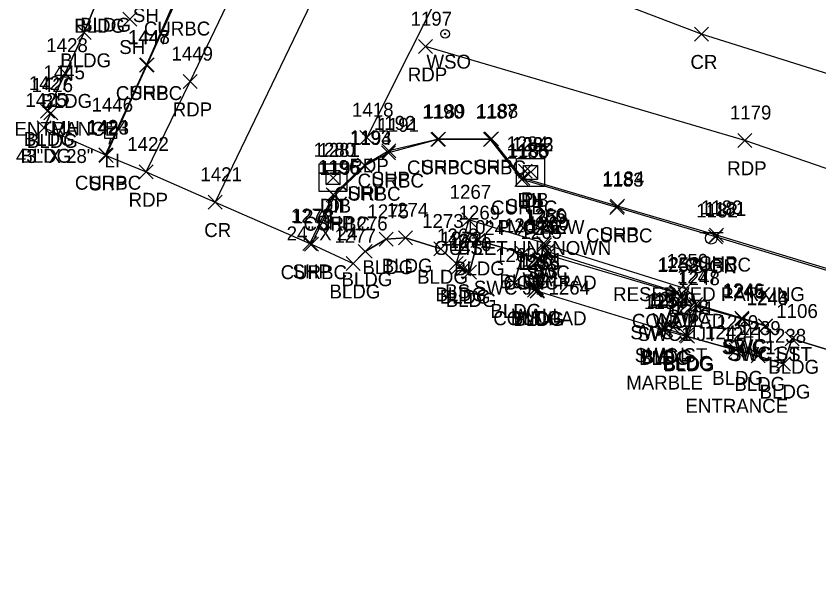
# Model space of a CAD drawing. Extents: x 1462668 to 1465147, y 550359 to 557351.
# Drawn here: x 1464553.4 to 1464668.5, y 552389.3 to 552470.8 of the extents above; entities that cross this region are included whole.
import ezdxf

# ---------------------------------------------------------------- set-up
doc = ezdxf.new("R2010")
doc.units = 0
for name, color, linetype in [('D_A', 7, 'Continuous'), ('D_C', 7, 'Continuous'), ('D_I', 7, 'Continuous'), ('D_TIC', 7, 'Continuous'), ('DS', 7, 'Continuous'), ('L_A', 7, 'Continuous'), ('L_C', 7, 'Continuous'), ('L_I', 7, 'Continuous'), ('L_TIC', 7, 'Continuous'), ('LBC', 7, 'Continuous'), ('LELB', 7, 'Continuous'), ('Level 6', 7, 'Continuous'), ('LS', 7, 'Continuous'), ('LW', 7, 'Continuous'), ('P_A', 7, 'Continuous'), ('P_I', 7, 'Continuous'), ('P_TIC', 7, 'Continuous'), ('PET', 7, 'Continuous'), ('PRC', 7, 'Continuous'), ('PSP', 7, 'Continuous'), ('R_A', 7, 'Continuous'), ('R_I', 7, 'Continuous'), ('R_TIC', 7, 'Continuous'), ('RC', 7, 'Continuous'), ('RSW', 7, 'Continuous'), ('S_A', 7, 'Continuous'), ('S_C', 7, 'Continuous'), ('S_I', 7, 'Continuous'), ('SSGN', 7, 'Continuous'), ('U_A', 7, 'Continuous'), ('U_C', 7, 'Continuous'), ('U_I', 7, 'Continuous'), ('ULP', 7, 'Continuous'), ('UUMH', 7, 'Continuous'), ('UWV', 7, 'Continuous')]:
    doc.layers.add(name, color=color, linetype=linetype)

msp = doc.modelspace()

# ---------------------------------------------------------------- linework, layer by layer
at = {"layer": 'D_TIC'}
for points in [[(1464597.88, 552446.64), (1464599.88, 552448.64)], [(1464599.88, 552446.64), (1464597.88, 552448.64)], [(1464625.43, 552447.58), (1464627.43, 552449.58)], [(1464627.43, 552447.58), (1464625.43, 552449.58)], [(1464626.22, 552447.48), (1464628.22, 552449.48)], [(1464628.22, 552447.48), (1464626.22, 552449.48)]]:
    msp.add_lwpolyline(points, dxfattribs=at)
at = {"layer": 'DS'}
for p, q in [((1464625.18, 552450.42), (1464629.18, 552450.42)), ((1464625.18, 552446.42), (1464625.18, 552450.42)), ((1464629.18, 552450.42), (1464629.18, 552446.42)), ((1464596.85, 552449.67), (1464600.85, 552449.67)), ((1464596.85, 552445.67), (1464596.85, 552449.67)), ((1464597.85, 552446.67), (1464597.85, 552448.67)), ((1464597.85, 552448.67), (1464599.85, 552448.67)), ((1464599.85, 552448.67), (1464599.85, 552446.67)), ((1464600.85, 552449.67), (1464600.85, 552445.67)), ((1464626.18, 552447.42), (1464626.18, 552449.42)), ((1464626.18, 552449.42), (1464628.18, 552449.42)), ((1464628.18, 552449.42), (1464628.18, 552447.42)), ((1464598.85, 552447.67), (1464598.85, 552447.67)), ((1464598.85, 552447.67), (1464598.85, 552447.67)), ((1464627.19, 552448.42), (1464627.19, 552448.42)), ((1464627.19, 552448.42), (1464627.19, 552448.42)), ((1464599.85, 552446.67), (1464597.85, 552446.67)), ((1464629.18, 552446.42), (1464625.18, 552446.42)), ((1464628.18, 552447.42), (1464626.18, 552447.42)), ((1464600.85, 552445.67), (1464596.85, 552445.67))]:
    msp.add_line(p, q, dxfattribs=at)
at = {"layer": 'L_TIC'}
for points in [[(1464568.73, 552469.4), (1464570.73, 552471.4)], [(1464570.73, 552469.4), (1464568.73, 552471.4)], [(1464562.16, 552467.49), (1464564.16, 552469.49)], [(1464564.16, 552467.49), (1464562.16, 552469.49)], [(1464559.44, 552461.67), (1464561.44, 552463.67)], [(1464561.44, 552461.67), (1464559.44, 552463.67)], [(1464556.94, 552456.22), (1464558.94, 552458.22)], [(1464558.94, 552456.22), (1464556.94, 552458.22)], [(1464557.38, 552455.94), (1464559.38, 552457.94)], [(1464559.38, 552455.94), (1464557.38, 552457.94)], [(1464556.45, 552453.8), (1464558.45, 552455.8)], [(1464558.45, 552453.8), (1464556.45, 552455.8)], [(1464617.32, 552440.63), (1464619.32, 552442.63)], [(1464619.32, 552440.63), (1464617.32, 552442.63)], [(1464605.48, 552437.83), (1464607.48, 552439.83)], [(1464607.48, 552437.83), (1464605.48, 552439.83)], [(1464608.25, 552438.05), (1464610.25, 552440.05)], [(1464610.25, 552438.05), (1464608.25, 552440.05)], [(1464618.61, 552437.65), (1464620.61, 552439.65)], [(1464620.61, 552437.65), (1464618.61, 552439.65)], [(1464613.32, 552436.45), (1464615.32, 552438.45)], [(1464615.32, 552436.45), (1464613.32, 552438.45)], [(1464628.07, 552437.27), (1464630.07, 552439.27)], [(1464630.07, 552437.27), (1464628.07, 552439.27)], [(1464602.48, 552436.1), (1464604.48, 552438.1)], [(1464604.48, 552436.1), (1464602.48, 552438.1)], [(1464625.11, 552435.81), (1464627.11, 552437.81)], [(1464627.11, 552435.81), (1464625.11, 552437.81)], [(1464628.53, 552436.1), (1464630.53, 552438.1)], [(1464630.53, 552436.1), (1464628.53, 552438.1)], [(1464628.64, 552435.62), (1464630.64, 552437.62)], [(1464630.64, 552435.62), (1464628.64, 552437.62)], [(1464600.76, 552434.34), (1464602.76, 552436.34)], [(1464602.76, 552434.34), (1464600.76, 552436.34)], [(1464615.5, 552434.37), (1464617.5, 552436.37)], [(1464617.5, 552434.37), (1464615.5, 552436.37)], [(1464615.95, 552433.93), (1464617.95, 552435.93)], [(1464617.95, 552433.93), (1464615.95, 552435.93)], [(1464616.56, 552433.6), (1464618.56, 552435.6)], [(1464618.56, 552433.6), (1464616.56, 552435.6)], [(1464617.42, 552433.13), (1464619.42, 552435.13)], [(1464619.42, 552433.13), (1464617.42, 552435.13)], [(1464623.84, 552431.56), (1464625.84, 552433.56)], [(1464625.84, 552431.56), (1464623.84, 552433.56)], [(1464626.73, 552430.54), (1464628.73, 552432.54)], [(1464628.73, 552430.54), (1464626.73, 552432.54)], [(1464627.01, 552430.88), (1464629.01, 552432.88)], [(1464629.01, 552430.88), (1464627.01, 552432.88)], [(1464627.19, 552430.5), (1464629.19, 552432.5)], [(1464629.19, 552430.5), (1464627.19, 552432.5)], [(1464627.12, 552430.4), (1464629.12, 552432.4)], [(1464629.12, 552430.4), (1464627.12, 552432.4)], [(1464647.05, 552430.14), (1464649.05, 552432.14)], [(1464649.05, 552430.14), (1464647.05, 552432.14)], [(1464647.17, 552430.26), (1464649.17, 552432.26)], [(1464649.17, 552430.26), (1464647.17, 552432.26)], [(1464645.15, 552424.82), (1464647.15, 552426.82)], [(1464647.15, 552424.82), (1464645.15, 552426.82)], [(1464645.33, 552425.28), (1464647.33, 552427.28)], [(1464647.33, 552425.28), (1464645.33, 552427.28)], [(1464645.51, 552424.99), (1464647.51, 552426.99)], [(1464647.51, 552424.99), (1464645.51, 552426.99)], [(1464648.5, 552424.09), (1464650.5, 552426.09)], [(1464650.5, 552424.09), (1464648.5, 552426.09)], [(1464648.66, 552423.91), (1464650.66, 552425.91)], [(1464650.66, 552423.91), (1464648.66, 552425.91)], [(1464663.67, 552423.54), (1464665.67, 552425.54)], [(1464665.67, 552423.54), (1464663.67, 552425.54)], [(1464655.63, 552421.95), (1464657.63, 552423.95)], [(1464657.63, 552421.95), (1464655.63, 552423.95)], [(1464658.8, 552421.09), (1464660.8, 552423.09)], [(1464660.8, 552421.09), (1464658.8, 552423.09)], [(1464662.42, 552419.98), (1464664.42, 552421.98)], [(1464664.42, 552419.98), (1464662.42, 552421.98)]]:
    msp.add_lwpolyline(points, dxfattribs=at)
at = {"layer": 'LBC'}
for points in [[(1464557.45, 552454.8), (1464558.38, 552456.94), (1464557.94, 552457.22), (1464560.44, 552462.67), (1464563.16, 552468.49), (1464565.17, 552473.45)], [(1464614.32, 552437.45), (1464609.25, 552439.05), (1464606.48, 552438.83), (1464603.48, 552437.1), (1464601.76, 552435.34)], [(1464675.46, 552421.24), (1464664.67, 552424.54), (1464663.42, 552420.98), (1464659.8, 552422.09), (1464656.63, 552422.95), (1464649.66, 552424.91), (1464649.5, 552425.09), (1464646.51, 552425.99), (1464646.15, 552425.82), (1464628.12, 552431.4), (1464627.73, 552431.54), (1464624.84, 552432.56), (1464626.11, 552436.81), (1464619.61, 552438.65), (1464618.42, 552434.13), (1464617.56, 552434.6), (1464616.95, 552434.93)], [(1464614.32, 552437.45), (1464616.5, 552435.37)], [(1464616.95, 552434.93), (1464616.5, 552435.37)]]:
    msp.add_lwpolyline(points, dxfattribs=at)
at = {"layer": 'LELB'}
msp.add_lwpolyline([(1464629.07, 552438.27), (1464618.32, 552441.63), (1464616.5, 552435.37)], dxfattribs=at)
at = {"layer": 'Level 6'}
msp.add_lwpolyline([(1464565.17, 552473.45), (1464563.16, 552468.49), (1464560.44, 552462.67), (1464557.94, 552457.22), (1464558.38, 552456.94), (1464557.45, 552454.8), (1464566.26, 552450.94), (1464566.35, 552450.84), (1464572.06, 552448.49), (1464581.96, 552444.15), (1464595.53, 552438.22), (1464595.76, 552438.11), (1464601.76, 552435.34), (1464603.48, 552437.1), (1464606.48, 552438.83), (1464609.25, 552439.05), (1464614.32, 552437.45), (1464616.5, 552435.37), (1464616.95, 552434.93), (1464617.56, 552434.6), (1464618.42, 552434.13), (1464619.61, 552438.65), (1464626.11, 552436.81), (1464624.84, 552432.56), (1464627.73, 552431.54), (1464628.12, 552431.4), (1464628.19, 552431.5), (1464629.64, 552436.62), (1464648.05, 552431.14), (1464646.15, 552425.82), (1464649.66, 552424.91), (1464656.63, 552422.95), (1464659.8, 552422.09), (1464663.42, 552420.98), (1464664.67, 552424.54), (1464675.46, 552421.24)], dxfattribs=at)
at = {"layer": 'LS'}
for points in [[(1464628.19, 552431.5), (1464629.64, 552436.62), (1464648.05, 552431.14)], [(1464648.05, 552431.14), (1464646.15, 552425.82)]]:
    msp.add_lwpolyline(points, dxfattribs=at)
at = {"layer": 'LW'}
msp.add_lwpolyline([(1464646.33, 552426.28), (1464648.17, 552431.26), (1464629.53, 552437.1), (1464628.01, 552431.88)], dxfattribs=at)
at = {"layer": 'P_TIC'}
for points in [[(1464650.67, 552467.26), (1464652.67, 552469.26)], [(1464652.67, 552467.26), (1464650.67, 552469.26)], [(1464611.1, 552465.46), (1464613.1, 552467.46)], [(1464613.1, 552465.46), (1464611.1, 552467.46)], [(1464571.2, 552462.84), (1464573.2, 552464.84)], [(1464573.2, 552462.84), (1464571.2, 552464.84)], [(1464577.39, 552460.45), (1464579.39, 552462.45)], [(1464579.39, 552460.45), (1464577.39, 552462.45)], [(1464602.71, 552452.41), (1464604.71, 552454.41)], [(1464604.71, 552452.41), (1464602.71, 552454.41)], [(1464613, 552452.2), (1464615, 552454.2)], [(1464615, 552452.2), (1464613, 552454.2)], [(1464620.57, 552452.25), (1464622.57, 552454.25)], [(1464622.57, 552452.25), (1464620.57, 552454.25)], [(1464656.88, 552452.01), (1464658.88, 552454.01)], [(1464658.88, 552452.01), (1464656.88, 552454.01)], [(1464605.85, 552450.52), (1464607.85, 552452.52)], [(1464607.85, 552450.52), (1464605.85, 552452.52)], [(1464565.35, 552449.84), (1464567.35, 552451.84)], [(1464567.35, 552449.84), (1464565.35, 552451.84)], [(1464602.38, 552448.44), (1464604.38, 552450.44)], [(1464604.38, 552448.44), (1464602.38, 552450.44)], [(1464571.06, 552447.49), (1464573.06, 552449.49)], [(1464573.06, 552447.49), (1464571.06, 552449.49)], [(1464625.06, 552446.61), (1464627.06, 552448.61)], [(1464627.06, 552446.61), (1464625.06, 552448.61)], [(1464580.96, 552443.15), (1464582.96, 552445.15)], [(1464582.96, 552443.15), (1464580.96, 552445.15)], [(1464597.87, 552444.19), (1464599.87, 552446.19)], [(1464599.87, 552444.19), (1464597.87, 552446.19)], [(1464638.64, 552442.56), (1464640.64, 552444.56)], [(1464640.64, 552442.56), (1464638.64, 552444.56)], [(1464652.82, 552438.4), (1464654.82, 552440.4)], [(1464654.82, 552438.4), (1464652.82, 552440.4)], [(1464594.53, 552437.22), (1464596.53, 552439.22)], [(1464596.53, 552437.22), (1464594.53, 552439.22)]]:
    msp.add_lwpolyline(points, dxfattribs=at)
at = {"layer": 'PET'}
for points in [[(1464572.06, 552448.49), (1464578.39, 552461.45), (1464597.78, 552501.89), (1464609.96, 552527.83), (1464625.75, 552562.93), (1464638.05, 552589.57), (1464661.76, 552635.83), (1464669.49, 552648.31)], [(1464688.81, 552609.87), (1464680.61, 552601.19), (1464673.86, 552589.46), (1464650.97, 552545.03), (1464631.53, 552508.13), (1464616.1, 552478.12), (1464603.71, 552453.41)], [(1464771.41, 552416.27), (1464733.17, 552427.87), (1464691.35, 552441.47), (1464657.88, 552453.01), (1464612.1, 552466.46)]]:
    msp.add_lwpolyline(points, dxfattribs=at)
at = {"layer": 'PRC'}
for points in [[(1464665.11, 552617.2), (1464647.94, 552582.04), (1464634.85, 552553.32), (1464610.76, 552505.16), (1464598.84, 552479.24), (1464581.96, 552444.15)], [(1464765.59, 552433.51), (1464734.74, 552442.75), (1464692.6, 552455.37), (1464651.67, 552468.26), (1464619.25, 552480.64)]]:
    msp.add_lwpolyline(points, dxfattribs=at)
at = {"layer": 'PSP'}
for points in [[(1464566.35, 552450.84), (1464572.2, 552463.84), (1464577.98, 552476.64), (1464591.94, 552507.35), (1464602.33, 552530.89), (1464618.43, 552566.28), (1464630.94, 552593.72), (1464653.16, 552635.86), (1464653.54, 552639.26)], [(1464771.87, 552416.15), (1464777.88, 552402.48), (1464762.83, 552406.18), (1464757.59, 552408.09), (1464728.85, 552416.86), (1464690.25, 552428.38), (1464653.82, 552439.4), (1464639.64, 552443.56), (1464626.06, 552447.61), (1464621.57, 552453.25), (1464614, 552453.2), (1464606.85, 552451.52), (1464603.38, 552449.44), (1464598.87, 552445.19), (1464595.53, 552438.22)]]:
    msp.add_lwpolyline(points, dxfattribs=at)
at = {"layer": 'R_TIC'}
for points in [[(1464571.13, 552462.79), (1464573.13, 552464.79)], [(1464573.13, 552462.79), (1464571.13, 552464.79)], [(1464612.87, 552452.13), (1464614.87, 552454.13)], [(1464614.87, 552452.13), (1464612.87, 552454.13)], [(1464620.43, 552452.14), (1464622.43, 552454.14)], [(1464622.43, 552452.14), (1464620.43, 552454.14)], [(1464605.79, 552450.24), (1464607.79, 552452.24)], [(1464607.79, 552450.24), (1464605.79, 552452.24)], [(1464565.26, 552449.94), (1464567.26, 552451.94)], [(1464567.26, 552449.94), (1464565.26, 552451.94)], [(1464602.44, 552448.36), (1464604.44, 552450.36)], [(1464604.44, 552448.36), (1464602.44, 552450.36)], [(1464624.93, 552446.39), (1464626.93, 552448.39)], [(1464626.93, 552446.39), (1464624.93, 552448.39)], [(1464598.05, 552444.06), (1464600.05, 552446.06)], [(1464600.05, 552444.06), (1464598.05, 552446.06)], [(1464638.56, 552442.38), (1464640.56, 552444.38)], [(1464640.56, 552442.38), (1464638.56, 552444.38)], [(1464652.69, 552438.19), (1464654.69, 552440.19)], [(1464654.69, 552438.19), (1464652.69, 552440.19)], [(1464594.76, 552437.11), (1464596.76, 552439.11)], [(1464596.76, 552437.11), (1464594.76, 552439.11)], [(1464628.2, 552437.06), (1464630.2, 552439.06)], [(1464630.2, 552437.06), (1464628.2, 552439.06)], [(1464627.47, 552434.89), (1464629.47, 552436.89)], [(1464629.47, 552434.89), (1464627.47, 552436.89)], [(1464648.46, 552430.73), (1464650.46, 552432.73)], [(1464650.46, 552430.73), (1464648.46, 552432.73)], [(1464649.85, 552428.49), (1464651.85, 552430.49)], [(1464651.85, 552428.49), (1464649.85, 552430.49)], [(1464650.05, 552428.25), (1464652.05, 552430.25)], [(1464652.05, 552428.25), (1464650.05, 552430.25)], [(1464656.46, 552426.5), (1464658.46, 552428.5)], [(1464658.46, 552426.5), (1464656.46, 552428.5)], [(1464656.54, 552426.35), (1464658.54, 552428.35)], [(1464658.54, 552426.35), (1464656.54, 552428.35)], [(1464646.61, 552425.2), (1464648.61, 552427.2)], [(1464648.61, 552425.2), (1464646.61, 552427.2)], [(1464659.86, 552425.36), (1464661.86, 552427.36)], [(1464661.86, 552425.36), (1464659.86, 552427.36)], [(1464659.87, 552425.44), (1464661.87, 552427.44)], [(1464661.87, 552425.44), (1464659.87, 552427.44)]]:
    msp.add_lwpolyline(points, dxfattribs=at)
at = {"layer": 'RC'}
for points in [[(1464566.26, 552450.94), (1464572.13, 552463.79), (1464576.16, 552473.05), (1464577.83, 552476.68), (1464591.72, 552507.48), (1464602.03, 552530.95), (1464618.29, 552566.35), (1464630.79, 552593.89), (1464652.95, 552635.9), (1464653.45, 552639.17), (1464652.02, 552641.3), (1464646.65, 552644.84)], [(1464770.34, 552389.26), (1464770.25, 552393.35), (1464768.02, 552401.44), (1464764.92, 552404.76), (1464762.74, 552406.07), (1464757.6, 552407.95), (1464728.8, 552416.54), (1464690.19, 552428.15), (1464653.69, 552439.19), (1464639.56, 552443.38), (1464625.93, 552447.39), (1464621.43, 552453.14), (1464613.87, 552453.13), (1464606.79, 552451.24), (1464603.44, 552449.36), (1464599.05, 552445.06), (1464595.76, 552438.11)]]:
    msp.add_lwpolyline(points, dxfattribs=at)
at = {"layer": 'RSW'}
for points in [[(1464647.61, 552426.2), (1464649.46, 552431.73), (1464629.2, 552438.06), (1464628.47, 552435.89)], [(1464628.47, 552435.89), (1464626.11, 552436.81)], [(1464650.85, 552429.49), (1464649.5, 552425.09)], [(1464651.05, 552429.25), (1464649.66, 552424.91)], [(1464660.87, 552426.44), (1464657.46, 552427.5), (1464650.85, 552429.49)], [(1464660.86, 552426.36), (1464657.54, 552427.35), (1464651.05, 552429.25)]]:
    msp.add_lwpolyline(points, dxfattribs=at)
at = {"layer": 'SSGN'}
for p, q in [((1464651.44, 552439.82), (1464654.77, 552439.82)), ((1464653.08, 552438.98), (1464653.08, 552438.98))]:
    msp.add_line(p, q, dxfattribs=at)
msp.add_circle((1464653.08, 552438.98), 0.833, dxfattribs=at)
at = {"layer": 'ULP'}
for p, q in [((1464567.15, 552455.8), (1464566.99, 552454.97)), ((1464566.15, 552453.3), (1464566.15, 552454.97)), ((1464566.15, 552454.97), (1464567.82, 552454.97)), ((1464567.82, 552454.97), (1464567.82, 552453.3)), ((1464567.82, 552453.3), (1464566.15, 552453.3)), ((1464566.74, 552452.47), (1464566.99, 552453.3)), ((1464566.99, 552454.13), (1464566.99, 552454.13))]:
    msp.add_line(p, q, dxfattribs=at)
at = {"layer": 'UUMH'}
for p, q in [((1464560.04, 552458.77), (1464560.04, 552458.77)), ((1464560.87, 552458.77), (1464560.87, 552458.77))]:
    msp.add_line(p, q, dxfattribs=at)
msp.add_circle((1464560.04, 552458.77), 0.833, dxfattribs=at)
at = {"layer": 'UWV'}
for radius in [0.625, 0.0833]:
    msp.add_circle((1464614.92, 552468.3), radius, dxfattribs=at)

# ---------------------------------------------------------------- texts
at = {"layer": 'D_A'}
for s, p in [('DIB', (1464625.32, 552443.48)), ('P', (1464625.8, 552443.58)), ('DI', (1464626.24, 552443.42)), ('DIB', (1464596.98, 552442.64)), ('DI', (1464597.91, 552442.67))]:
    msp.add_text(s, height=2, dxfattribs=at).set_placement(p)
at = {"layer": 'D_C'}
for s, p in [('24" X 24"', (1464592.21, 552438.67)), ('10" PVC NEW', (1464617.75, 552439.58)), ('24" X 24"', (1464620.54, 552439.42)), ('OUTLET UNKNOWN', (1464613.35, 552436.58))]:
    msp.add_text(s, height=2, dxfattribs=at).set_placement(p)
at = {"layer": 'D_I'}
for s, p in [('1284', (1464623.73, 552451.58)), ('1282', (1464624.49, 552451.42)), ('1283', (1464624.52, 552451.48)), ('1280', (1464596.07, 552450.67)), ('1281', (1464596.75, 552450.64))]:
    msp.add_text(s, height=2, dxfattribs=at).set_placement(p)
at = {"layer": 'L_A'}
for s, p in [('SH', (1464570.16, 552469.98)), ('BLDG', (1464561.76, 552468.45)), ('BLDG', (1464562.6, 552468.59)), ('SH', (1464568.21, 552465.4)), ('BLDG', (1464559.75, 552463.49)), ('BLDG', (1464557.03, 552457.67)), ('BLDG', (1464554.53, 552452.22)), ('BLDG', (1464554.97, 552451.94)), ('BLDG', (1464554.04, 552449.8)), ('BS', (1464616.76, 552436.63)), ('BLDG', (1464605.84, 552434.05)), ('BLDG', (1464603.07, 552433.83)), ('BLDG', (1464616.2, 552433.65)), ('BS', (1464627.51, 552433.27)), ('BLDG', (1464600.07, 552432.1)), ('BLDG', (1464610.91, 552432.45)), ('BLDG', (1464622.7, 552431.81)), ('CONCPAD', (1464623.28, 552431.62)), ('WALL', (1464626.02, 552432.1)), ('BLDG', (1464598.35, 552430.34)), ('BLDG', (1464613.54, 552429.93)), ('BLDG', (1464614.15, 552429.6)), ('BS', (1464614.94, 552430.37)), ('BLDG', (1464615.01, 552429.13)), ('BLDG', (1464621.43, 552427.56)), ('CONCPAD', (1464621.83, 552426.5)), ('WALL', (1464624.5, 552426.88)), ('BLDG', (1464624.32, 552426.54)), ('BLDG', (1464624.71, 552426.4)), ('CONCPAD', (1464641.7, 552426.14)), ('WALL', (1464644.65, 552426.26)), ('WALL', (1464642.82, 552421.28)), ('BLDG', (1464642.74, 552420.82)), ('BLDG', (1464643.1, 552420.99)), ('BLDG', (1464646.09, 552420.09)), ('BLDG', (1464646.25, 552419.91)), ('BLDG', (1464661.26, 552419.54)), ('BLDG', (1464653.22, 552417.95)), ('BLDG', (1464656.39, 552417.09)), ('BLDG', (1464660.01, 552415.98))]:
    msp.add_text(s, height=2, dxfattribs=at).set_placement(p)
at = {"layer": 'L_C'}
for s, p in [('ENTRANCE', (1464553.19, 552453.67)), ('MARBLE', (1464640.89, 552417.28)), ('ENTRANCE', (1464649.39, 552413.95))]:
    msp.add_text(s, height=2, dxfattribs=at).set_placement(p)
at = {"layer": 'L_I'}
for s, p in [('1428', (1464557.75, 552465.67)), ('1427', (1464555.25, 552460.22)), ('1426', (1464555.63, 552459.94)), ('1425', (1464554.75, 552457.8)), ('1267', (1464615.58, 552444.63)), ('1274', (1464606.56, 552442.05)), ('1275', (1464603.79, 552441.83)), ('1269', (1464616.86, 552441.65)), ('1266', (1464626.27, 552441.27)), ('1276', (1464600.73, 552440.1)), ('1273', (1464611.63, 552440.45)), ('1264', (1464623.37, 552439.81)), ('1260', (1464626.71, 552440.1)), ('1257', (1464626.94, 552439.62)), ('1277', (1464599.06, 552438.34)), ('1268', (1464613.76, 552438.37)), ('1272', (1464614.26, 552437.93)), ('1271', (1464615.43, 552437.6)), ('1270', (1464615.64, 552437.13)), ('1263', (1464622.1, 552435.56)), ('1262', (1464624.99, 552434.54)), ('1255', (1464625.42, 552434.4)), ('1256', (1464625.44, 552434.5)), ('1261', (1464625.83, 552434.88)), ('1258', (1464645.36, 552434.14)), ('1252', (1464645.47, 552434.26)), ('1251', (1464644.21, 552429.28)), ('1254', (1464643.45, 552428.82)), ('1253', (1464643.82, 552428.99)), ('1242', (1464646.8, 552428.09)), ('1241', (1464647.53, 552427.91)), ('1106', (1464662.41, 552427.54)), ('1240', (1464653.85, 552425.95)), ('1239', (1464657.09, 552425.09)), ('1238', (1464660.73, 552423.98))]:
    msp.add_text(s, height=2, dxfattribs=at).set_placement(p)
at = {"layer": 'P_A'}
for s, p in [('CR', (1464650.1, 552463.26)), ('RDP', (1464609.58, 552461.46)), ('SHP', (1464569.74, 552458.84)), ('RDP', (1464575.88, 552456.45)), ('RDP', (1464601.2, 552448.41)), ('SHP', (1464611.53, 552448.2)), ('SHP', (1464619.11, 552448.25)), ('RDP', (1464655.37, 552448.01)), ('SHP', (1464563.88, 552445.84)), ('SHP', (1464604.39, 552446.52)), ('SHP', (1464600.91, 552444.44)), ('RDP', (1464569.55, 552443.49)), ('SHP', (1464623.6, 552442.61)), ('SHP', (1464596.4, 552440.19)), ('CR', (1464580.39, 552439.15)), ('SHP', (1464637.18, 552438.56)), ('SHP', (1464651.35, 552434.4)), ('SHP', (1464593.06, 552433.22))]:
    msp.add_text(s, height=2, dxfattribs=at).set_placement(p)
at = {"layer": 'P_I'}
for s, p in [('1197', (1464609.97, 552469.46)), ('1448', (1464569.51, 552466.84)), ('1449', (1464575.69, 552464.45)), ('1418', (1464601.58, 552456.41)), ('1189', (1464611.86, 552456.2)), ('1188', (1464619.45, 552456.25)), ('1179', (1464655.75, 552456.01)), ('1423', (1464563.66, 552453.84)), ('1192', (1464604.72, 552454.52)), ('1193', (1464601.25, 552452.44)), ('1422', (1464569.36, 552451.49)), ('1185', (1464623.93, 552450.61)), ('1196', (1464596.69, 552448.19)), ('1421', (1464579.84, 552447.15)), ('1184', (1464637.52, 552446.56)), ('1180', (1464651.6, 552442.4)), ('1279', (1464592.82, 552441.22))]:
    msp.add_text(s, height=2, dxfattribs=at).set_placement(p)
at = {"layer": 'R_A'}
for s, p in [('CURBC', (1464571.74, 552468.05)), ('CURBC', (1464567.72, 552458.79)), ('CURBC', (1464609.46, 552448.13)), ('CURBC', (1464617.01, 552448.14)), ('CURBC', (1464561.85, 552445.94)), ('CURBC', (1464602.38, 552446.24)), ('CURBC', (1464599.03, 552444.36)), ('CURBC', (1464621.51, 552442.39)), ('CURBC', (1464594.63, 552440.06)), ('CURBC', (1464635.14, 552438.38)), ('CURBC', (1464649.27, 552434.19)), ('CURBC', (1464591.35, 552433.11)), ('SWC', (1464626.56, 552433.06)), ('SWC JT 1264', (1464619.05, 552430.89)), ('SWC', (1464646.82, 552426.73)), ('SWC JT 1242', (1464641.48, 552424.49)), ('SWC1 JT 1241', (1464642.53, 552424.25)), ('SWC', (1464654.82, 552422.5)), ('SWC1', (1464654.58, 552422.35)), ('SWC ST', (1464655.36, 552421.44)), ('SWC1 ST', (1464655.64, 552421.36)), ('SWC ST', (1464642.11, 552421.2))]:
    msp.add_text(s, height=2, dxfattribs=at).set_placement(p)
at = {"layer": 'R_I'}
for s, p in [('1447', (1464569.44, 552466.79)), ('1190', (1464611.66, 552456.13)), ('1187', (1464619.31, 552456.14)), ('1424', (1464563.57, 552453.94)), ('1191', (1464605.23, 552454.24)), ('1194', (1464601.32, 552452.36)), ('1186', (1464623.75, 552450.39)), ('1195', (1464596.92, 552448.06)), ('1183', (1464637.43, 552446.38)), ('1181', (1464652.13, 552442.19)), ('1278', (1464593.07, 552441.11)), ('1259', (1464626.5, 552441.06)), ('1265', (1464625.73, 552438.89)), ('1250', (1464646.68, 552434.73)), ('1247', (1464648.15, 552432.49)), ('1248', (1464648.36, 552432.25)), ('1246', (1464654.71, 552430.5)), ('1245', (1464654.85, 552430.35)), ('1244', (1464658.17, 552429.36)), ('1243', (1464658.17, 552429.44)), ('1249', (1464644.91, 552429.2))]:
    msp.add_text(s, height=2, dxfattribs=at).set_placement(p)
at = {"layer": 'S_A'}
msp.add_text('SIGN', height=2, dxfattribs=at).set_placement((1464650.22, 552433.96))
at = {"layer": 'S_C'}
msp.add_text('RESERVED PARKING', height=2, dxfattribs=at).set_placement((1464639.01, 552429.96))
at = {"layer": 'S_I'}
msp.add_text('1182', height=2, dxfattribs=at).set_placement((1464650.94, 552441.96))
at = {"layer": 'U_A'}
for s, p in [('WSO', (1464612.25, 552463.3)), ('MH', (1464558.4, 552453.77)), ('LI', (1464566.09, 552449.13))]:
    msp.add_text(s, height=2, dxfattribs=at).set_placement(p)
at = {"layer": 'U_C'}
msp.add_text('43" X 28"', height=2, dxfattribs=at).set_placement((1464553.39, 552449.77))
at = {"layer": 'U_I'}
for s, p in [('1445', (1464557.34, 552461.77)), ('1446', (1464564.24, 552457.13))]:
    msp.add_text(s, height=2, dxfattribs=at).set_placement(p)

doc.saveas('drawing.dxf')
